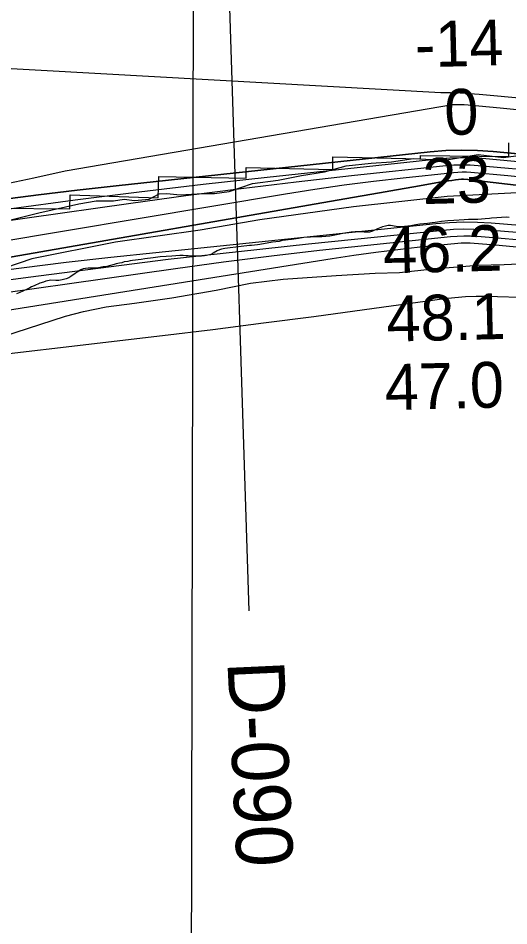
# Model space of a CAD drawing. Extents: x 3192986 to 3230865, y 867483 to 892886.
# Drawn here: x 3207396 to 3208113, y 876124 to 877451 of the extents above; entities that cross this region are included whole.
import ezdxf

# ---------------------------------------------------------------- set-up
doc = ezdxf.new("R2010")
doc.units = 0
for name, color, linetype in [('V-GRID-MAJR', 7, 'Continuous'), ('V-RIVR-EDGE', 7, 'Continuous'), ('V-RIVR-RANG', 7, 'Continuous'), ('V-RIVR-RANG-IDEN', 7, 'Continuous'), ('V-ROAD-CNTR', 7, 'Continuous'), ('V-RRAP-FSHR', 7, 'Continuous'), ('V-RRAP-RVMT', 7, 'Continuous'), ('V-SITE-VEGE', 7, 'Continuous'), ('V-TOPO-DPTH', 7, 'Continuous'), ('V-TOPO-MAJR', 7, 'Continuous'), ('V-TOPO-MINR', 7, 'Continuous'), ('V-TOPO-WATR', 7, 'Continuous')]:
    doc.layers.add(name, color=color, linetype=linetype)

msp = doc.modelspace()

# ---------------------------------------------------------------- linework, layer by layer
at = {"layer": 'V-GRID-MAJR'}
msp.add_spline([(3207642.5, 872901.1), (3207654.8, 878960.7), (3207667.2, 885023.3), (3207679.5, 891086), (3207679.5, 891089.1)], degree=3, dxfattribs=at)
at = {"layer": 'V-RIVR-EDGE'}
msp.add_lwpolyline([(3207347.3, 877147.3), (3207425.6, 877166.6), (3207484.3, 877179.8), (3207509.5, 877184.1), (3207534.8, 877184.5), (3207550.6, 877186.8), (3207565.8, 877184.9), (3207587.3, 877186.7), (3207601.6, 877194.8), (3207613, 877195.2), (3207632.6, 877193.3), (3207665.5, 877195.1), (3207682.7, 877195.1), (3207704.1, 877197.9), (3207738, 877209.7), (3207775.7, 877214.4), (3207810.1, 877221.5), (3207843.5, 877226.6), (3207875.4, 877235.6), (3207911.7, 877239.3), (3207941.7, 877241.2), (3207973.7, 877246.3), (3208000.9, 877244.8), (3208021.8, 877244.3), (3208068.1, 877252.3), (3208105.3, 877247.9), (3208123.4, 877250.3)], dxfattribs=at)
at = {"layer": 'V-RIVR-RANG'}
msp.add_line((3207733.4, 876584.9), (3207693, 877844.2), dxfattribs=at)
at = {"layer": 'V-ROAD-CNTR'}
msp.add_lwpolyline([(3207354.6, 876980), (3207465, 877015.5), (3207490.9, 877022.4), (3207524.4, 877029.5), (3207565.5, 877034.5), (3207620.2, 877042.5), (3207685, 877053.6), (3207735.2, 877064), (3207782.9, 877069.7), (3207860.6, 877075.1), (3207917.5, 877078.6), (3207953.2, 877079.6), (3208001.7, 877084.8), (3208068.3, 877090.1), (3208106.2, 877091.2), (3208139, 877092.9)], dxfattribs=at)
at = {"layer": 'V-RRAP-FSHR'}
msp.add_lwpolyline([(3208709.4, 877295.1), (3208642.2, 877289.3), (3208500.6, 877278), (3208401.1, 877257.7), (3208300.9, 877225.7), (3208230, 877206), (3208162.7, 877197.9), (3208022.7, 877190.5), (3207885.8, 877175.6), (3207749, 877156.3), (3207661.5, 877141.4), (3207537.8, 877123.8), (3207415.4, 877099.7), (3207299.3, 877060), (3207201.5, 877039), (3207060.6, 877025.9), (3206947.1, 877024.1), (3206849.3, 877028.8), (3206731.4, 877032.2), (3206612.7, 877018.8)], dxfattribs=at)
at = {"layer": 'V-RRAP-RVMT'}
for p, q in [((3208112.9, 877249.4), (3208113.1, 877269)), ((3207855.7, 877230), (3207855.9, 877248.5)), ((3207855.9, 877248.5), (3207984.1, 877245.8)), ((3207984.1, 877245.8), (3207984.1, 877250.5)), ((3207984.1, 877250.5), (3208112.9, 877249.4)), ((3207728.9, 877217.4), (3207728.8, 877233)), ((3207728.8, 877233), (3207855.7, 877230)), ((3207600.2, 877188.7), (3207601.3, 877219.7)), ((3207601.3, 877219.7), (3207728.9, 877217.4)), ((3207470.9, 877172.6), (3207471.4, 877193.1)), ((3207471.4, 877193.1), (3207600.2, 877188.7)), ((3207341.1, 877173.9), (3207470.9, 877172.6))]:
    msp.add_line(p, q, dxfattribs=at)
at = {"layer": 'V-SITE-VEGE'}
for p, q in [((3208032.5, 877155.8), (3208023.8, 877155.2)), ((3208047.7, 877156.4), (3208032.5, 877155.8)), ((3208053.9, 877156.8), (3208047.7, 877156.4)), ((3208058.4, 877156.8), (3208053.9, 877156.8)), ((3208064.4, 877157.2), (3208058.4, 877156.8)), ((3208067.7, 877157.2), (3208064.4, 877157.2)), ((3208078.2, 877158.1), (3208067.7, 877157.2)), ((3208084.8, 877158.5), (3208078.2, 877158.1)), ((3208087.7, 877159.1), (3208084.8, 877158.5)), ((3208095.4, 877159.7), (3208087.7, 877159.1)), ((3208108.9, 877160.3), (3208095.4, 877159.7)), ((3208113.3, 877160.1), (3208108.9, 877160.3)), ((3207921, 877143.3), (3207913.8, 877139.8)), ((3207928.1, 877146.3), (3207921, 877143.3)), ((3207932.7, 877147.5), (3207928.1, 877146.3)), ((3207936.4, 877148.1), (3207932.7, 877147.5)), ((3207939.8, 877148.1), (3207936.4, 877148.1)), ((3207948.3, 877146.7), (3207939.8, 877148.1)), ((3207952.5, 877146.3), (3207948.3, 877146.7)), ((3207957.2, 877146.3), (3207952.5, 877146.3)), ((3207960.4, 877146.9), (3207957.2, 877146.3)), ((3207969.5, 877147.9), (3207960.4, 877146.9)), ((3207977.2, 877149.3), (3207969.5, 877147.9)), ((3207982.8, 877150), (3207977.2, 877149.3)), ((3207993.9, 877151.4), (3207982.8, 877150)), ((3208000.8, 877152), (3207993.9, 877151.4)), ((3208005.1, 877152.6), (3208000.8, 877152)), ((3208008.9, 877153), (3208005.1, 877152.6)), ((3208014.6, 877154), (3208008.9, 877153)), ((3208023.8, 877155.2), (3208014.6, 877154)), ((3207805.7, 877129.3), (3207795.2, 877127.9)), ((3207813.4, 877130.5), (3207805.7, 877129.3)), ((3207833, 877131.8), (3207813.4, 877130.5)), ((3207839.6, 877131.8), (3207833, 877131.8)), ((3207851.1, 877132.8), (3207839.6, 877131.8)), ((3207866.1, 877135.8), (3207851.1, 877132.8)), ((3207870.1, 877136.4), (3207866.1, 877135.8)), ((3207873.2, 877137), (3207870.1, 877136.4)), ((3207882.4, 877138.4), (3207873.2, 877137)), ((3207888.5, 877138.8), (3207882.4, 877138.4)), ((3207892.4, 877139.2), (3207888.5, 877138.8)), ((3207896.6, 877139), (3207892.4, 877139.2)), ((3207901.4, 877138.6), (3207896.6, 877139)), ((3207906.1, 877138.4), (3207901.4, 877138.6)), ((3207909.3, 877138.6), (3207906.1, 877138.4)), ((3207913.8, 877139.8), (3207909.3, 877138.6)), ((3207721.7, 877117.6), (3207697.6, 877114.8)), ((3207733.6, 877119.2), (3207721.7, 877117.6)), ((3207736.8, 877119.2), (3207733.6, 877119.2)), ((3207745.5, 877120), (3207736.8, 877119.2)), ((3207748.9, 877120.4), (3207745.5, 877120)), ((3207767.3, 877124.1), (3207748.9, 877120.4)), ((3207777.2, 877125.1), (3207767.3, 877124.1)), ((3207781.7, 877126.1), (3207777.2, 877125.1)), ((3207786.3, 877126.7), (3207781.7, 877126.1)), ((3207790.6, 877127.1), (3207786.3, 877126.7)), ((3207795.2, 877127.9), (3207790.6, 877127.1)), ((3207612.2, 877103), (3207603.3, 877102.2)), ((3207620.1, 877103.4), (3207612.2, 877103)), ((3207631.8, 877104.3), (3207620.1, 877103.4)), ((3207637, 877104.3), (3207631.8, 877104.3)), ((3207640.9, 877104), (3207637, 877104.3)), ((3207644.3, 877104), (3207640.9, 877104)), ((3207650.2, 877103.6), (3207644.3, 877104)), ((3207655.4, 877103.4), (3207650.2, 877103.6)), ((3207663.7, 877103.4), (3207655.4, 877103.4)), ((3207668.1, 877103.7), (3207663.7, 877103.4)), ((3207671, 877104.3), (3207668.1, 877103.7)), ((3207677.4, 877105.9), (3207671, 877104.3)), ((3207680.7, 877107.7), (3207677.4, 877105.9)), ((3207686.5, 877111.3), (3207680.7, 877107.7)), ((3207689.8, 877112.7), (3207686.5, 877111.3)), ((3207692.8, 877113.6), (3207689.8, 877112.7)), ((3207697.6, 877114.8), (3207692.8, 877113.6)), ((3207535.8, 877091.1), (3207525.3, 877088.3)), ((3207539.1, 877092.1), (3207535.8, 877091.1)), ((3207543.9, 877093.1), (3207539.1, 877092.1)), ((3207547.1, 877093.9), (3207543.9, 877093.1)), ((3207550.4, 877094.9), (3207547.1, 877093.9)), ((3207555.8, 877095.8), (3207550.4, 877094.9)), ((3207559.1, 877096.6), (3207555.8, 877095.8)), ((3207562.9, 877097.2), (3207559.1, 877096.6)), ((3207575.4, 877098.6), (3207562.9, 877097.2)), ((3207580.9, 877099.4), (3207575.4, 877098.6)), ((3207593, 877100.8), (3207580.9, 877099.4)), ((3207603.3, 877102.2), (3207593, 877100.8)), ((3207479.1, 877078), (3207472.8, 877073.5)), ((3207481.7, 877080), (3207479.1, 877078)), ((3207487.2, 877083.6), (3207481.7, 877080)), ((3207490.6, 877084.8), (3207487.2, 877083.6)), ((3207494.2, 877085.6), (3207490.6, 877084.8)), ((3207497.9, 877085.8), (3207494.2, 877085.6)), ((3207506.8, 877085.8), (3207497.9, 877085.8)), ((3207510.6, 877085.9), (3207506.8, 877085.8)), ((3207519.9, 877087.7), (3207510.6, 877085.9)), ((3207525.3, 877088.3), (3207519.9, 877087.7)), ((3207427.4, 877063.8), (3207418.9, 877060.2)), ((3207432.4, 877065.4), (3207427.4, 877063.8)), ((3207435.9, 877066.8), (3207432.4, 877065.4)), ((3207443.5, 877068.3), (3207435.9, 877066.8)), ((3207450.8, 877067.9), (3207443.5, 877068.3)), ((3207455, 877067.9), (3207450.8, 877067.9)), ((3207459.7, 877068.7), (3207455, 877067.9)), ((3207465.5, 877070.3), (3207459.7, 877068.7)), ((3207469.8, 877071.9), (3207465.5, 877070.3)), ((3207472.8, 877073.5), (3207469.8, 877071.9)), ((3207398.1, 877050.3), (3207393, 877048.3)), ((3207402.3, 877052.1), (3207398.1, 877050.3)), ((3207409.6, 877055.5), (3207402.3, 877052.1)), ((3207412.4, 877057.2), (3207409.6, 877055.5)), ((3207415.1, 877058.4), (3207412.4, 877057.2)), ((3207418.9, 877060.2), (3207415.1, 877058.4))]:
    msp.add_line(p, q, dxfattribs=at)
at = {"layer": 'V-TOPO-DPTH'}
for points in [[(3206883.1, 877455.1), (3206885, 877448.2), (3206890.5, 877443.5), (3206898.3, 877440.3), (3207143.7, 877424.8), (3207161.8, 877423.1), (3207179.7, 877420.4), (3207197.4, 877416.5), (3207214.9, 877411.8), (3207233.3, 877406.1), (3207260.1, 877398.4), (3207287, 877391.3), (3207314.1, 877385.4), (3207341.5, 877380.1), (3208013.5, 877342.7), (3208027.6, 877342.6), (3208041.7, 877342.1), (3208055.8, 877341.3), (3208069.9, 877340.2), (3208208.2, 877327.7), (3208223.9, 877326.2)], [(3206883.1, 877455.1), (3206885, 877448.2), (3206890.5, 877443.5), (3206898.3, 877440.3), (3207143.7, 877424.8), (3207161.8, 877423.1), (3207179.7, 877420.4), (3207197.4, 877416.5), (3207214.9, 877411.8), (3207233.3, 877406.1), (3207260.1, 877398.4), (3207287, 877391.3), (3207314.1, 877385.4), (3207341.5, 877380.1), (3208013.5, 877342.7), (3208027.6, 877342.6), (3208041.7, 877342.1), (3208055.8, 877341.3), (3208069.9, 877340.2), (3208208.2, 877327.7)], [(3208223.9, 877326.2), (3208215.9, 877244.6), (3208090, 877256.5), (3208067, 877258), (3208043.9, 877258.5), (3208020.9, 877257.7), (3207997.8, 877255.9), (3207538.9, 877206.5), (3207482, 877200.1), (3207425.1, 877193.3), (3207368.3, 877186), (3207311.5, 877178.4), (3207222, 877165.9), (3207210.1, 877164.4), (3207198.1, 877163), (3207186, 877161.9), (3207174, 877161), (3207045.9, 877152.3), (3206969.8, 877147.2), (3206893.6, 877142.1), (3206817.5, 877137.2), (3206741.4, 877132.3), (3206546.5, 877119.9)], [(3208464.8, 877221), (3208090, 877256.5), (3208067, 877258), (3208043.9, 877258.5), (3208020.9, 877257.7), (3207997.8, 877255.9), (3207538.9, 877206.5), (3207482, 877200.1), (3207425.1, 877193.3), (3207368.3, 877186), (3207311.5, 877178.4), (3207222, 877165.9), (3207210.1, 877164.4), (3207198.1, 877163), (3207186, 877161.9), (3207174, 877161), (3207045.9, 877152.3), (3206969.8, 877147.2), (3206893.6, 877142.1), (3206817.5, 877137.2), (3206741.4, 877132.3), (3206546.5, 877119.9)], [(3206658.7, 877088.8), (3206686.5, 877090.8), (3207143.3, 877125.5), (3207171.7, 877127.9), (3207200.1, 877130.8), (3207228.4, 877134.1), (3207256.6, 877137.8), (3207560.5, 877181), (3207640.9, 877192), (3207721.5, 877202.5), (3207802.2, 877212.1), (3207882.9, 877221.2), (3208020.7, 877235.9), (3208032.6, 877236.8), (3208044.5, 877237.2), (3208056.4, 877237), (3208068.3, 877236.2), (3208168.2, 877227.1)], [(3206658.7, 877088.8), (3206686.5, 877090.8), (3207143.3, 877125.5), (3207171.7, 877127.9), (3207200.1, 877130.8), (3207228.4, 877134.1), (3207256.6, 877137.8), (3207560.5, 877181), (3207640.9, 877192), (3207721.5, 877202.5), (3207802.2, 877212.1), (3207882.9, 877221.2), (3208020.7, 877235.9), (3208032.6, 877236.8), (3208044.5, 877237.2), (3208056.4, 877237), (3208068.3, 877236.2), (3208168.2, 877227.1)], [(3208530.3, 877159.9), (3208069.2, 877213.7), (3208065.1, 877214.1), (3208061.1, 877214.5), (3208057.1, 877214.9), (3208053.1, 877215.3), (3208046.6, 877215.9), (3208045.8, 877215.9), (3208043.6, 877215.9), (3208034.9, 877214.9), (3208029.8, 877214.3), (3208024.7, 877213.7), (3208019.6, 877212.9), (3208014.5, 877212.1), (3207974.2, 877205), (3207948.9, 877200.5), (3207923.7, 877196.1), (3207898.4, 877191.7), (3207873.2, 877187.3), (3207375.5, 877100.6)]]:
    msp.add_lwpolyline(points, dxfattribs=at)
at = {"layer": 'V-TOPO-MAJR'}
msp.add_lwpolyline([(3206658.9, 876977.1), (3206722.3, 876982.2), (3206785.6, 876987.6), (3206848.9, 876993.1), (3206912.2, 876998.9), (3207146.1, 877020.6), (3207176.4, 877023.6), (3207206.6, 877026.9), (3207236.8, 877030.7), (3207266.9, 877034.7), (3207625.6, 877085.5), (3207695.7, 877095), (3207765.9, 877104), (3207836.1, 877112.1), (3207906.5, 877119.7), (3208027.8, 877132.1), (3208037.5, 877132.8), (3208047.2, 877133.2), (3208057, 877133), (3208066.7, 877132.5), (3208159.9, 877124.9)], dxfattribs=at)
at = {"layer": 'V-TOPO-MINR'}
for points in [[(3206883.1, 877455.1), (3206885, 877448.2), (3206890.5, 877443.5), (3206898.3, 877440.3), (3207143.7, 877424.8), (3207161.8, 877423.1), (3207179.7, 877420.4), (3207197.4, 877416.5), (3207214.9, 877411.8), (3207233.3, 877406.1), (3207260.1, 877398.4), (3207287, 877391.3), (3207314.1, 877385.4), (3207341.5, 877380.1), (3208013.5, 877342.7), (3208027.6, 877342.6), (3208041.7, 877342.1), (3208055.8, 877341.3), (3208069.9, 877340.2), (3208208.2, 877327.7)], [(3207372.2, 877208.3), (3207418.4, 877218.1), (3207464.5, 877228.3), (3208030.8, 877325), (3208036.5, 877325.3), (3208042.2, 877325.4), (3208047.9, 877325.2), (3208053.5, 877324.8), (3208100.4, 877320.5), (3208129.5, 877317.6)], [(3206546.5, 877119.9), (3206741.4, 877132.3), (3206817.5, 877137.2), (3206893.6, 877142.1), (3206969.8, 877147.2), (3207045.9, 877152.3), (3207174, 877161), (3207186, 877161.9), (3207198.1, 877163), (3207210.1, 877164.4), (3207222, 877165.9), (3207311.5, 877178.4), (3207368.3, 877186), (3207425.1, 877193.3), (3207482, 877200.1), (3207538.9, 877206.5), (3207997.8, 877255.9), (3208020.9, 877257.7), (3208043.9, 877258.5), (3208067, 877258), (3208090, 877256.5), (3208464.8, 877221)], [(3206644.2, 877107.8), (3206686.5, 877111.1), (3206728.8, 877114.2), (3206771.1, 877117.3), (3207159.6, 877144.5), (3207179.3, 877146.1), (3207199, 877147.9), (3207218.6, 877150.2), (3207238.2, 877152.7), (3207385.7, 877173.1), (3207479.1, 877185.6), (3207572.5, 877197.6), (3207666.1, 877208.6), (3207759.7, 877219.1), (3208009.3, 877245.9), (3208026.7, 877247.2), (3208044.2, 877247.9), (3208061.7, 877247.5), (3208079.2, 877246.4), (3208304.6, 877225.4)], [(3206589.6, 877057.9), (3207056.6, 877084.1), (3207080.9, 877085.7), (3207105.2, 877087.4), (3207129.5, 877089.5), (3207153.8, 877091.8), (3207178, 877094.5), (3207202.1, 877097.5), (3207226.3, 877101), (3207250.3, 877104.8), (3207786.4, 877194.5), (3207829.3, 877201.3), (3207872.2, 877207.6), (3207915.3, 877213), (3207958.4, 877218), (3208032.1, 877225.9), (3208038.5, 877226.4), (3208044.8, 877226.6), (3208051.1, 877226.5), (3208057.4, 877226.1), (3208111.6, 877221.2), (3208145.1, 877218.1)], [(3207375.5, 877100.6), (3207873.2, 877187.3), (3207898.4, 877191.7), (3207923.7, 877196.1), (3207948.9, 877200.5), (3207974.2, 877205), (3208014.5, 877212.1), (3208019.6, 877212.9), (3208024.7, 877213.7), (3208029.8, 877214.3), (3208034.9, 877214.9), (3208043.6, 877215.9), (3208045.8, 877215.9), (3208046.6, 877215.9), (3208053.1, 877215.3), (3208057.1, 877214.9), (3208061.1, 877214.5), (3208065.1, 877214.1), (3208069.2, 877213.7), (3208530.3, 877159.9)], [(3206549.7, 877011), (3206680.6, 877020.8), (3206757.2, 877026.5), (3206833.8, 877032.3), (3206910.4, 877038), (3206987, 877043.8), (3207177.9, 877058.2), (3207191.2, 877059.3), (3207204.5, 877060.6), (3207217.8, 877062.1), (3207231, 877063.8), (3207335.1, 877077.9), (3207400.4, 877086.4), (3207465.8, 877094.5), (3207531.3, 877101.9), (3207596.8, 877109), (3208006.1, 877151.1), (3208026.4, 877152.7), (3208046.7, 877153.5), (3208067, 877153.1), (3208087.3, 877152), (3208482.7, 877120)], [(3206666, 877004.1), (3207164, 877042.2), (3207184.7, 877043.9), (3207205.4, 877045.9), (3207226.1, 877048.3), (3207246.8, 877050.9), (3207410.1, 877072.9), (3207512.5, 877086.1), (3207615, 877098.8), (3207717.5, 877110.4), (3207820.2, 877121.4), (3208016.9, 877141.6), (3208031.9, 877142.7), (3208047, 877143.3), (3208062, 877143.1), (3208077, 877142.3), (3208297.2, 877124.4)], [(3206581, 876936.6), (3207089.9, 876983.5), (3207109.7, 876985.4), (3207129.5, 876987.4), (3207149.3, 876989.7), (3207169, 876992.1), (3207188.8, 876994.7), (3207208.5, 876997.4), (3207228.2, 877000.3), (3207247.8, 877003.4), (3207854.5, 877100.1), (3207886.5, 877104.9), (3207918.6, 877109.4), (3207950.8, 877113.3), (3207983, 877116.9), (3208038.7, 877122.5), (3208043.1, 877122.9), (3208047.5, 877123), (3208051.9, 877123), (3208056.4, 877122.7), (3208098.7, 877119.3), (3208124.3, 877116.9)], [(3206631.4, 876907.3), (3206677.1, 876910.9), (3206722.9, 876914.2), (3206768.7, 876917.1), (3206814.5, 876919.8), (3207166.1, 876938.7), (3207189.1, 876940.2), (3207212, 876941.9), (3207234.9, 876944.1), (3207257.7, 876946.6), (3207606.4, 876987.5), (3207680.4, 876996.4), (3207754.3, 877005.7), (3207828.1, 877015.3), (3207902, 877025.3), (3208018.8, 877041.4), (3208034.2, 877043.1), (3208049.6, 877044.3), (3208065.1, 877044.7), (3208080.5, 877044.7), (3208469.1, 877033.1)]]:
    msp.add_lwpolyline(points, dxfattribs=at)
at = {"layer": 'V-TOPO-WATR'}
msp.add_lwpolyline([(3206658.7, 877088.8), (3206686.5, 877090.8), (3207143.3, 877125.5), (3207171.7, 877127.9), (3207200.1, 877130.8), (3207228.4, 877134.1), (3207256.6, 877137.8), (3207560.5, 877181), (3207640.9, 877192), (3207721.5, 877202.5), (3207802.2, 877212.1), (3207882.9, 877221.2), (3208020.7, 877235.9), (3208032.6, 877236.8), (3208044.5, 877237.2), (3208056.4, 877237), (3208068.3, 877236.2), (3208168.2, 877227.1)], dxfattribs=at)

# ---------------------------------------------------------------- texts
at = {"layer": 'V-RIVR-RANG'}
for s, rotation, p in [('-14', 1.5181, (3207976.4, 877379.3)), ('0', 1.5181, (3208019.6, 877280.4)), ('23', 1.5181, (3207987.7, 877179.5)), ('46.2', 1.3583, (3207929.9, 877078.2)), ('48.1', 1.3583, (3207934.8, 876978.3)), ('47.0', 1.3583, (3207932.2, 876878.2))]:
    msp.add_text(s, height=67, rotation=rotation, dxfattribs=at).set_placement(p)
at = {"layer": 'V-RIVR-RANG-IDEN'}
msp.add_text('D-090', height=83, rotation=272.6312, dxfattribs=at).set_placement((3207701.5, 876510.4))

doc.saveas('drawing.dxf')
